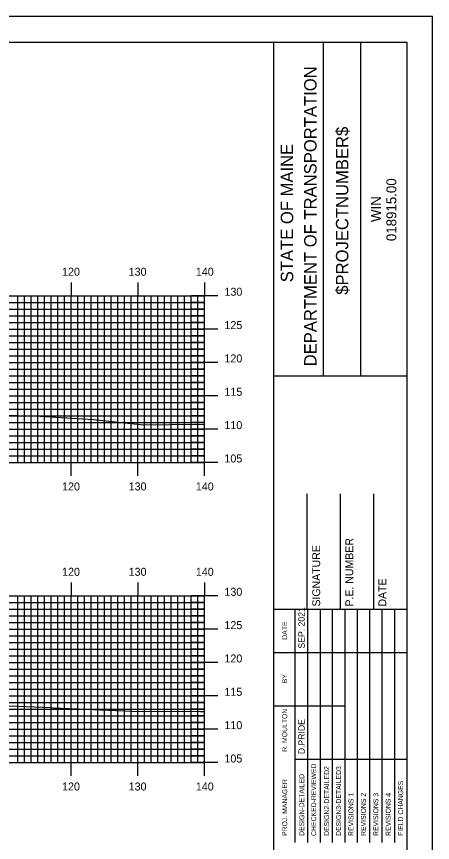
# Model space of a CAD drawing. Extents: x 1780680 to 1781023, y 442591 to 442811.
# Drawn here: x 1780957.2 to 1781019.6, y 442686.7 to 442810.5 of the extents above; entities that cross this region are included whole.
import ezdxf

# ---------------------------------------------------------------- set-up
doc = ezdxf.new("R2010")
doc.units = 0
for name, color, linetype in [('BORDER', 7, 'Continuous'), ('H_V ANNOTATION', 7, 'Continuous'), ('MAJOR', 7, 'Continuous'), ('MINOR', 7, 'Continuous'), ('PLOT BOUNDARY', 7, 'Continuous'), ('S_Roadway_Centerline', 7, 'Continuous')]:
    doc.layers.add(name, color=color, linetype=linetype)

msp = doc.modelspace()

# ---------------------------------------------------------------- linework, layer by layer
at = {"layer": 'BORDER'}
for p, q in [((1780995.78, 442596.67), (1780995.78, 442806.67)), ((1781003.24, 442756.66), (1781003.24, 442806.66)), ((1781008.83, 442756.66), (1781008.83, 442806.66)), ((1780995.78, 442756.65), (1781015.78, 442756.65)), ((1781000.78, 442721.67), (1781000.78, 442738.97)), ((1781005.78, 442721.67), (1781005.78, 442738.97)), ((1781010.78, 442721.67), (1781010.78, 442738.97)), ((1780995.78, 442721.67), (1781015.78, 442721.67))]:
    msp.add_line(p, q, dxfattribs=at)
msp.add_lwpolyline([(1780695.78, 442596.67), (1781015.78, 442596.67), (1781015.78, 442806.67), (1780695.78, 442806.67)], close=True, dxfattribs=at)
for points in [[(1780999.01, 442715.17), (1780999.01, 442721.67)], [(1781000.88, 442686.68), (1781000.88, 442721.67)], [(1781002.74, 442721.67), (1781002.74, 442686.68)], [(1781004.6, 442686.68), (1781004.6, 442721.67)], [(1781006.47, 442686.68), (1781006.47, 442721.67)], [(1781008.33, 442686.68), (1781008.33, 442721.67)], [(1781010.19, 442686.68), (1781010.19, 442721.67)], [(1781012.06, 442686.68), (1781012.06, 442721.67)], [(1781013.92, 442686.68), (1781013.92, 442721.67)], [(1780999.01, 442686.68), (1780999.01, 442720.26)], [(1780995.78, 442715.17), (1781015.78, 442715.17)], [(1780995.78, 442707.17), (1780999.01, 442707.17)], [(1780999.01, 442707.17), (1781006.46, 442707.17)], [(1780999.01, 442699.17), (1781015.78, 442699.17)]]:
    msp.add_lwpolyline(points, dxfattribs=at)
at = {"layer": 'MAJOR'}
for p, q in [((1780965.38, 442770.67), (1780965.38, 442768.67)), ((1780975.38, 442770.67), (1780975.38, 442768.67)), ((1780985.38, 442770.67), (1780985.38, 442768.67)), ((1780705.38, 442768.67), (1780985.38, 442768.67)), ((1780705.38, 442768.67), (1780985.38, 442768.67)), ((1780965.38, 442743.67), (1780965.38, 442768.67)), ((1780975.38, 442743.67), (1780975.38, 442768.67)), ((1780987.39, 442768.67), (1780983.38, 442768.67)), ((1780985.38, 442743.67), (1780985.38, 442768.67)), ((1780985.38, 442743.67), (1780985.38, 442768.67)), ((1780705.38, 442763.67), (1780985.38, 442763.67)), ((1780987.39, 442763.67), (1780983.38, 442763.67)), ((1780705.38, 442758.67), (1780985.38, 442758.67)), ((1780987.39, 442758.67), (1780983.38, 442758.67)), ((1780705.38, 442753.67), (1780985.38, 442753.67)), ((1780987.39, 442753.67), (1780983.38, 442753.67)), ((1780705.38, 442748.67), (1780985.38, 442748.67)), ((1780987.39, 442748.67), (1780983.38, 442748.67)), ((1780705.38, 442743.67), (1780985.38, 442743.67)), ((1780705.38, 442743.67), (1780985.38, 442743.67)), ((1780965.38, 442741.66), (1780965.38, 442743.67)), ((1780975.38, 442741.66), (1780975.38, 442743.67)), ((1780987.39, 442743.67), (1780983.38, 442743.67)), ((1780985.38, 442741.66), (1780985.38, 442743.67)), ((1780965.38, 442725.67), (1780965.38, 442723.67)), ((1780975.38, 442725.67), (1780975.38, 442723.67)), ((1780985.38, 442725.67), (1780985.38, 442723.67)), ((1780705.38, 442723.67), (1780985.38, 442723.67)), ((1780705.38, 442723.67), (1780985.38, 442723.67)), ((1780965.38, 442698.67), (1780965.38, 442723.67)), ((1780975.38, 442698.67), (1780975.38, 442723.67)), ((1780987.39, 442723.67), (1780983.38, 442723.67)), ((1780985.38, 442698.67), (1780985.38, 442723.67)), ((1780985.38, 442698.67), (1780985.38, 442723.67)), ((1780705.38, 442718.67), (1780985.38, 442718.67)), ((1780987.39, 442718.67), (1780983.38, 442718.67)), ((1780705.38, 442713.67), (1780985.38, 442713.67)), ((1780987.39, 442713.67), (1780983.38, 442713.67)), ((1780705.38, 442708.67), (1780985.38, 442708.67)), ((1780987.39, 442708.67), (1780983.38, 442708.67)), ((1780705.38, 442703.67), (1780985.38, 442703.67)), ((1780987.39, 442703.67), (1780983.38, 442703.67)), ((1780705.38, 442698.67), (1780985.38, 442698.67)), ((1780705.38, 442698.67), (1780985.38, 442698.67)), ((1780965.38, 442696.66), (1780965.38, 442698.67)), ((1780975.38, 442696.66), (1780975.38, 442698.67)), ((1780987.39, 442698.67), (1780983.38, 442698.67)), ((1780985.38, 442696.66), (1780985.38, 442698.67))]:
    msp.add_line(p, q, dxfattribs=at)
at = {"layer": 'MINOR'}
for p, q in [((1780957.38, 442743.67), (1780957.38, 442768.67)), ((1780958.38, 442743.67), (1780958.38, 442768.67)), ((1780959.38, 442743.67), (1780959.38, 442768.67)), ((1780960.38, 442743.67), (1780960.38, 442768.67)), ((1780961.38, 442743.67), (1780961.38, 442768.67)), ((1780962.38, 442743.67), (1780962.38, 442768.67)), ((1780963.38, 442743.67), (1780963.38, 442768.67)), ((1780964.38, 442743.67), (1780964.38, 442768.67)), ((1780966.38, 442743.67), (1780966.38, 442768.67)), ((1780967.38, 442743.67), (1780967.38, 442768.67)), ((1780968.38, 442743.67), (1780968.38, 442768.67)), ((1780969.38, 442743.67), (1780969.38, 442768.67)), ((1780970.38, 442743.67), (1780970.38, 442768.67)), ((1780971.38, 442743.67), (1780971.38, 442768.67)), ((1780972.38, 442743.67), (1780972.38, 442768.67)), ((1780973.38, 442743.67), (1780973.38, 442768.67)), ((1780974.38, 442743.67), (1780974.38, 442768.67)), ((1780976.38, 442743.67), (1780976.38, 442768.67)), ((1780977.38, 442743.67), (1780977.38, 442768.67)), ((1780978.38, 442743.67), (1780978.38, 442768.67)), ((1780979.38, 442743.67), (1780979.38, 442768.67)), ((1780980.38, 442743.67), (1780980.38, 442768.67)), ((1780981.38, 442743.67), (1780981.38, 442768.67)), ((1780982.38, 442743.67), (1780982.38, 442768.67)), ((1780983.38, 442743.67), (1780983.38, 442768.67)), ((1780984.38, 442743.67), (1780984.38, 442768.67)), ((1780705.38, 442767.67), (1780985.38, 442767.67)), ((1780985.38, 442767.67), (1780983.38, 442767.67)), ((1780705.38, 442766.67), (1780985.38, 442766.67)), ((1780985.38, 442766.67), (1780983.38, 442766.67)), ((1780705.38, 442765.67), (1780985.38, 442765.67)), ((1780985.38, 442765.67), (1780983.38, 442765.67)), ((1780705.38, 442764.67), (1780985.38, 442764.67)), ((1780985.38, 442764.67), (1780983.38, 442764.67)), ((1780705.38, 442762.67), (1780985.38, 442762.67)), ((1780985.38, 442762.67), (1780983.38, 442762.67)), ((1780705.38, 442761.67), (1780985.38, 442761.67)), ((1780985.38, 442761.67), (1780983.38, 442761.67)), ((1780705.38, 442760.67), (1780985.38, 442760.67)), ((1780985.38, 442760.67), (1780983.38, 442760.67)), ((1780705.38, 442759.67), (1780985.38, 442759.67)), ((1780985.38, 442759.67), (1780983.38, 442759.67)), ((1780705.38, 442757.67), (1780985.38, 442757.67)), ((1780985.38, 442757.67), (1780983.38, 442757.67)), ((1780705.38, 442756.67), (1780985.38, 442756.67)), ((1780985.38, 442756.67), (1780983.38, 442756.67)), ((1780705.38, 442755.67), (1780985.38, 442755.67)), ((1780985.38, 442755.67), (1780983.38, 442755.67)), ((1780705.38, 442754.67), (1780985.38, 442754.67)), ((1780985.38, 442754.67), (1780983.38, 442754.67)), ((1780705.38, 442752.67), (1780985.38, 442752.67)), ((1780985.38, 442752.67), (1780983.38, 442752.67)), ((1780705.38, 442751.67), (1780985.38, 442751.67)), ((1780985.38, 442751.67), (1780983.38, 442751.67)), ((1780705.38, 442750.67), (1780985.38, 442750.67)), ((1780985.38, 442750.67), (1780983.38, 442750.67)), ((1780705.38, 442749.67), (1780985.38, 442749.67)), ((1780985.38, 442749.67), (1780983.38, 442749.67)), ((1780705.38, 442747.67), (1780985.38, 442747.67)), ((1780985.38, 442747.67), (1780983.38, 442747.67)), ((1780705.38, 442746.67), (1780985.38, 442746.67)), ((1780985.38, 442746.67), (1780983.38, 442746.67)), ((1780705.38, 442745.67), (1780985.38, 442745.67)), ((1780985.38, 442745.67), (1780983.38, 442745.67)), ((1780705.38, 442744.67), (1780985.38, 442744.67)), ((1780985.38, 442744.67), (1780983.38, 442744.67)), ((1780957.38, 442698.67), (1780957.38, 442723.67)), ((1780958.38, 442698.67), (1780958.38, 442723.67)), ((1780959.38, 442698.67), (1780959.38, 442723.67)), ((1780960.38, 442698.67), (1780960.38, 442723.67)), ((1780961.38, 442698.67), (1780961.38, 442723.67)), ((1780962.38, 442698.67), (1780962.38, 442723.67)), ((1780963.38, 442698.67), (1780963.38, 442723.67)), ((1780964.38, 442698.67), (1780964.38, 442723.67)), ((1780966.38, 442698.67), (1780966.38, 442723.67)), ((1780967.38, 442698.67), (1780967.38, 442723.67)), ((1780968.38, 442698.67), (1780968.38, 442723.67)), ((1780969.38, 442698.67), (1780969.38, 442723.67)), ((1780970.38, 442698.67), (1780970.38, 442723.67)), ((1780971.38, 442698.67), (1780971.38, 442723.67)), ((1780972.38, 442698.67), (1780972.38, 442723.67)), ((1780973.38, 442698.67), (1780973.38, 442723.67)), ((1780974.38, 442698.67), (1780974.38, 442723.67)), ((1780976.38, 442698.67), (1780976.38, 442723.67)), ((1780977.38, 442698.67), (1780977.38, 442723.67)), ((1780978.38, 442698.67), (1780978.38, 442723.67)), ((1780979.38, 442698.67), (1780979.38, 442723.67)), ((1780980.38, 442698.67), (1780980.38, 442723.67)), ((1780981.38, 442698.67), (1780981.38, 442723.67)), ((1780982.38, 442698.67), (1780982.38, 442723.67)), ((1780983.38, 442698.67), (1780983.38, 442723.67)), ((1780984.38, 442698.67), (1780984.38, 442723.67)), ((1780705.38, 442722.67), (1780985.38, 442722.67)), ((1780705.38, 442721.67), (1780985.38, 442721.67)), ((1780985.38, 442722.67), (1780983.38, 442722.67)), ((1780985.38, 442721.67), (1780983.38, 442721.67)), ((1780705.38, 442720.67), (1780985.38, 442720.67)), ((1780985.38, 442720.67), (1780983.38, 442720.67)), ((1780705.38, 442719.67), (1780985.38, 442719.67)), ((1780985.38, 442719.67), (1780983.38, 442719.67)), ((1780705.38, 442717.67), (1780985.38, 442717.67)), ((1780705.38, 442716.67), (1780985.38, 442716.67)), ((1780985.38, 442717.67), (1780983.38, 442717.67)), ((1780985.38, 442716.67), (1780983.38, 442716.67)), ((1780705.38, 442715.67), (1780985.38, 442715.67)), ((1780985.38, 442715.67), (1780983.38, 442715.67)), ((1780705.38, 442714.67), (1780985.38, 442714.67)), ((1780985.38, 442714.67), (1780983.38, 442714.67)), ((1780705.38, 442712.67), (1780985.38, 442712.67)), ((1780705.38, 442711.67), (1780985.38, 442711.67)), ((1780985.38, 442712.67), (1780983.38, 442712.67)), ((1780985.38, 442711.67), (1780983.38, 442711.67)), ((1780705.38, 442710.67), (1780985.38, 442710.67)), ((1780985.38, 442710.67), (1780983.38, 442710.67)), ((1780705.38, 442709.67), (1780985.38, 442709.67)), ((1780985.38, 442709.67), (1780983.38, 442709.67)), ((1780705.38, 442707.67), (1780985.38, 442707.67)), ((1780705.38, 442706.67), (1780985.38, 442706.67)), ((1780985.38, 442707.67), (1780983.38, 442707.67)), ((1780985.38, 442706.67), (1780983.38, 442706.67)), ((1780705.38, 442705.67), (1780985.38, 442705.67)), ((1780985.38, 442705.67), (1780983.38, 442705.67)), ((1780705.38, 442704.67), (1780985.38, 442704.67)), ((1780985.38, 442704.67), (1780983.38, 442704.67)), ((1780705.38, 442702.67), (1780985.38, 442702.67)), ((1780705.38, 442701.67), (1780985.38, 442701.67)), ((1780985.38, 442702.67), (1780983.38, 442702.67)), ((1780985.38, 442701.67), (1780983.38, 442701.67)), ((1780705.38, 442700.67), (1780985.38, 442700.67)), ((1780985.38, 442700.67), (1780983.38, 442700.67)), ((1780705.38, 442699.67), (1780985.38, 442699.67)), ((1780985.38, 442699.67), (1780983.38, 442699.67))]:
    msp.add_line(p, q, dxfattribs=at)
at = {"layer": 'PLOT BOUNDARY'}
msp.add_lwpolyline([(1780679.59, 442590.55), (1781019.59, 442590.55), (1781019.59, 442810.55), (1780679.59, 442810.55)], close=True, dxfattribs=at)
at = {"layer": 'S_Roadway_Centerline'}
for points in [[(1780893.56, 442752.35), (1780894.93, 442752.37), (1780896.39, 442752.34), (1780909.57, 442752.25), (1780926.04, 442751.41), (1780937.83, 442751.12), (1780943.94, 442750.97), (1780959.88, 442750.68), (1780968.72, 442750.1), (1780976.21, 442749.3), (1780984.09, 442749.4), (1780985.38, 442749.36)], [(1780893.94, 442709.16), (1780895.49, 442709.14), (1780915.02, 442708.5), (1780918.2, 442708.4), (1780927.97, 442707.99), (1780938.58, 442707.66), (1780939.79, 442707.63), (1780950.99, 442707.37), (1780962.4, 442706.9), (1780962.78, 442706.88), (1780974.48, 442706.35), (1780984.78, 442706.34), (1780985.38, 442706.32)]]:
    msp.add_lwpolyline(points, dxfattribs=at)

# ---------------------------------------------------------------- texts
at = {"layer": 'BORDER'}
for s, height, p in [('DEPARTMENT OF TRANSPORTATION', 1.8635, (1781002.2, 442758.08)), ('$PROJECTNUMBER$', 1.8635, (1781006.97, 442768.82)), ('STATE OF MAINE', 1.8635, (1780998.69, 442770.69)), ('018915.00', 1.491, (1781014.17, 442776.86)), ('WIN', 1.491, (1781011.86, 442779.73)), ('P.E. NUMBER', 1.1811, (1781007.7, 442722.06)), ('SIGNATURE', 1.181, (1781002.74, 442722.06)), ('DATE', 1.181, (1781012.66, 442722.06)), ('SEP. 2021', 0.969, (1781000.43, 442715.76)), ('DATE', 0.743, (1780997.79, 442717.08)), ('BY', 0.743, (1780997.79, 442710.54)), ('R. MOULTON', 0.745, (1780997.79, 442700.28)), ('D.PRIDE', 0.969, (1781000.43, 442699.92)), ('CHECKED-REVIEWED', 0.7455, (1781002.14, 442687.65)), ('DESIGN2-DETAILED2', 0.7455, (1781004.08, 442687.65)), ('DESIGN3-DETAILED3', 0.7455, (1781005.87, 442687.65)), ('PROJ. MANAGER', 0.7455, (1780997.79, 442687.65)), ('DESIGN-DETAILED', 0.7455, (1781000.35, 442687.65)), ('FIELD CHANGES', 0.7455, (1781015.19, 442687.65)), ('REVISIONS 1', 0.7455, (1781007.73, 442687.65)), ('REVISIONS 2', 0.7455, (1781009.6, 442687.65)), ('REVISIONS 3', 0.7455, (1781011.46, 442687.65)), ('REVISIONS 4', 0.7455, (1781013.32, 442687.65))]:
    msp.add_text(s, height=height, rotation=90, dxfattribs=at).set_placement(p)
at = {"layer": 'H_V ANNOTATION'}
for s, p in [('120', (1780964.02, 442771.67)), ('130', (1780974.01, 442771.67)), ('140', (1780984.09, 442771.67)), ('130', (1780988.38, 442768.67)), ('125', (1780988.38, 442763.67)), ('120', (1780988.38, 442758.67)), ('115', (1780988.38, 442753.67)), ('110', (1780988.38, 442748.67)), ('105', (1780988.38, 442743.67)), ('120', (1780964.02, 442739.47)), ('130', (1780974.01, 442739.47)), ('140', (1780984.09, 442739.47)), ('120', (1780964.02, 442726.67)), ('130', (1780974.01, 442726.67)), ('140', (1780984.09, 442726.67)), ('130', (1780988.38, 442723.67)), ('125', (1780988.38, 442718.67)), ('120', (1780988.38, 442713.67)), ('115', (1780988.38, 442708.67)), ('110', (1780988.38, 442703.67)), ('105', (1780988.38, 442698.67)), ('120', (1780964.02, 442694.47)), ('130', (1780974.01, 442694.47)), ('140', (1780984.09, 442694.47))]:
    msp.add_text(s, height=1.2, dxfattribs=at).set_placement(p)

doc.saveas('drawing.dxf')
